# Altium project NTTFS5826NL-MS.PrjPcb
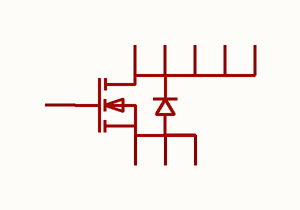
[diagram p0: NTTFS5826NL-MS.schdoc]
1 sheet, 1 parts. Net scope: global (net labels, ports and power ports of the same name join across sheets).

## Sheet NTTFS5826NL-MS.schdoc
size 127 x 101 mm

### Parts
Q?  nttfs5826nl-ms  [DFN-8_L3.2-W3.1-P0.65-LS3.4-BL]  (value not drawn)

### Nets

Not connected (* = marked no-connect by the designer): Q? 1(S) 2(S) 3(S) 4(G) 5(D) 6(D) 7(D) 8(D) 9(D)

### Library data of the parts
Q? = nttfs5826nl-ms: 数量:1个N沟道;漏源电压(Vdss):60V;连续漏极电流(Id):20A;导通电阻(RDS(on)):-;耗散功率(Pd):34.7W;阈值电压(Vgs(th)):2.5V;; Manufacturer: MSKSEMI(美森科); AddInBom: yes; ModelId: 516601acd9f9456f95db3aec763cd5e7; ModelName: PDFN3333-8_L3.1-W3.2-H0.8-P0.65; ModelTransform: 129.921,131.8895,0,0,0,0,0,0,0; Number: 1个N沟道; Drain to Source Voltage: 60V; Current - Continuous Drain(Id): 20A; Pd - Power Dissipation: 34.7W; Gate Threshold Voltage (Vgs(th)): 2.5V; Gate Charge(Qg): 20.3nC@10V; Input Capacitance(Ciss): 1.148nF; Reverse Transfer Capacitance (Crss@Vds): 49.4pF; Type: N沟道; Output Capacitance(Coss): 58.5pF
